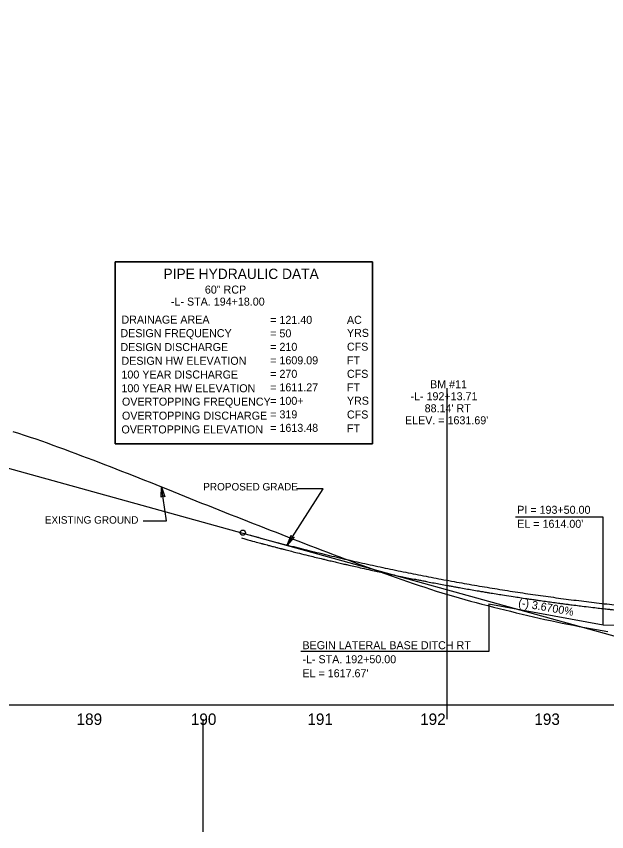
# Model space of a CAD drawing. Extents: x 498575 to 532350, y 405181 to 484585.
# Drawn here: x 523656 to 524172, y 483123 to 483836 of the extents above; entities that cross this region are included whole.
import ezdxf

# ---------------------------------------------------------------- set-up
doc = ezdxf.new("R2010")
doc.units = 0
for name, color, linetype in [('Exist Profile Cell', 7, 'Continuous'), ('Exist Vertical Profile Ground Line', 7, 'Continuous'), ('Exist Vertical Profile Horizontal Axis Label Major', 7, 'Continuous'), ('Prop Grid Mask', 7, 'Continuous'), ('Prop PFL Text', 7, 'Continuous'), ('Prop Vertical Profile Curve Label', 7, 'Continuous'), ('Prop Vertical Profile Ditch Grade Right', 7, 'Continuous'), ('Prop Vertical Profile Ditch Grade Right Label', 7, 'Continuous'), ('Prop Vertical Profile Grade', 7, 'Continuous'), ('Prop VPI Label', 7, 'Continuous'), ('Scratch_Level_0', 7, 'Continuous'), ('Scratch_Level_6', 7, 'Continuous'), ('Sheet Data Text CELL', 7, 'Continuous'), ('Sheet Profile Grid Minor CELL', 7, 'Continuous')]:
    doc.layers.add(name, color=color, linetype=linetype)

msp = doc.modelspace()

# ---------------------------------------------------------------- linework, layer by layer
at = {"layer": 'Exist Profile Cell'}
msp.add_line((505856.74, 483233.71), (526056.74, 483233.71), dxfattribs=at)
at = {"layer": 'Exist Vertical Profile Ground Line'}
for points in [[(523653.15, 483472.83), (523658.15, 483471.2), (523663.15, 483469.54), (523668.15, 483467.88), (523673.15, 483466.16), (523678.15, 483464.44), (523683.15, 483462.67), (523688.15, 483460.89), (523693.15, 483459.08), (523698.15, 483457.21), (523703.15, 483455.32), (523708.15, 483453.42), (523713.15, 483451.55), (523718.15, 483449.7), (523723.15, 483447.82), (523728.15, 483445.91), (523733.15, 483443.99), (523738.15, 483442.05), (523743.15, 483440.07), (523748.15, 483438.1), (523753.15, 483436.15), (523758.15, 483434.19), (523763.15, 483432.26), (523768.15, 483430.3), (523773.15, 483428.31), (523778.15, 483426.32), (523783.15, 483424.31), (523788.15, 483422.3), (523793.15, 483420.26), (523798.15, 483418.2), (523803.15, 483416.18), (523808.15, 483414.15), (523813.15, 483412.15)], [(523813.15, 483412.15), (523818.15, 483410.17), (523823.15, 483408.19), (523828.15, 483406.19), (523833.15, 483404.2), (523838.15, 483402.21), (523843.15, 483400.22), (523848.15, 483398.26), (523853.15, 483396.29), (523858.15, 483394.33), (523863.15, 483392.39), (523868.15, 483390.42), (523873.15, 483388.47), (523878.15, 483386.52), (523883.15, 483384.57), (523888.15, 483382.6), (523893.15, 483380.65), (523898.15, 483378.72), (523903.15, 483376.76), (523908.15, 483374.8), (523913.15, 483372.85), (523918.15, 483370.92), (523923.15, 483369), (523928.15, 483367.1), (523933.15, 483365.23), (523938.15, 483363.34), (523943.15, 483361.49), (523948.15, 483359.62), (523953.15, 483357.75), (523958.15, 483355.89), (523963.15, 483354.07), (523968.15, 483352.29), (523973.15, 483350.47), (523978.15, 483348.69), (523983.15, 483346.9), (523988.15, 483345.15), (523993.15, 483343.38), (523998.15, 483341.61), (524003.15, 483339.89), (524008.15, 483338.19), (524013.15, 483336.52), (524018.15, 483334.89), (524023.15, 483333.28), (524028.15, 483331.73), (524033.15, 483330.21), (524038.15, 483328.73), (524043.15, 483327.3), (524048.15, 483325.89), (524053.15, 483324.49), (524058.15, 483323.13), (524063.15, 483321.79), (524068.15, 483320.52), (524073.15, 483319.22), (524078.15, 483318), (524083.15, 483316.78), (524088.15, 483315.55), (524093.15, 483314.32), (524098.15, 483313.1), (524103.15, 483311.9), (524108.15, 483310.76), (524113.15, 483309.6), (524118.15, 483308.45), (524123.15, 483307.38), (524128.15, 483306.34), (524133.15, 483305.29), (524138.15, 483304.3), (524143.15, 483303.32), (524148.15, 483302.35), (524153.15, 483301.42), (524158.15, 483300.49), (524163.15, 483299.58), (524168.15, 483298.72), (524173.15, 483297.84)]]:
    msp.add_lwpolyline(points, dxfattribs=at)
at = {"layer": 'Prop Grid Mask'}
msp.add_lwpolyline([(523742.45, 483620.91), (523967.45, 483620.91), (523967.45, 483461.91), (523742.45, 483461.91)], close=True, dxfattribs=at)
at = {"layer": 'Prop PFL Text'}
for p, q in [((523787.28, 483394.7), (523783.15, 483424.31)), ((523892.93, 483373.48), (523924.46, 483422.67)), ((523924.46, 483422.67), (523901.04, 483422.67)), ((523766.92, 483394.7), (523787.28, 483394.7))]:
    msp.add_line(p, q, dxfattribs=at)
for points in [[(523782.87, 483415.19), (523783.15, 483424.31), (523785.99, 483415.57), (523784.25, 483416.49)], [(523899.04, 483380.27), (523892.93, 483373.48), (523896.4, 483381.99), (523897.14, 483380.16)]]:
    msp.add_lwpolyline(points, close=True, dxfattribs=at)
at = {"layer": 'Prop Vertical Profile Curve Label'}
msp.add_circle((523854.08, 483384.26), 2.25, dxfattribs=at)
at = {"layer": 'Prop Vertical Profile Ditch Grade Right'}
msp.add_lwpolyline([(524069.08, 483322.06), (524169.08, 483303.71), (524239.08, 483302.66), (524239.08, 483302.66)], dxfattribs=at)
at = {"layer": 'Prop Vertical Profile Ditch Grade Right Label'}
for p, q in [((524169.08, 483397.85), (524092.59, 483397.85)), ((524169.08, 483303.71), (524169.08, 483397.85)), ((524069.08, 483322.06), (524069.08, 483280.47)), ((524069.08, 483280.47), (523904.91, 483280.47))]:
    msp.add_line(p, q, dxfattribs=at)
at = {"layer": 'Prop Vertical Profile Grade'}
msp.add_line((522224.08, 483835.63), (523854.08, 483383.86), dxfattribs=at)
msp.add_spline([(523854.08, 483383.86), (523871.88, 483379), (523889.68, 483374.32), (523907.48, 483369.8), (523925.28, 483365.44), (523943.08, 483361.24), (523960.88, 483357.22), (523978.68, 483353.35), (523996.48, 483349.65), (524014.28, 483346.12), (524032.08, 483342.75), (524049.88, 483339.54), (524067.68, 483336.5), (524085.48, 483333.62), (524103.28, 483330.91), (524121.08, 483328.36), (524138.88, 483325.98), (524156.68, 483323.76), (524174.48, 483321.71), (524192.28, 483319.82), (524210.08, 483318.09), (524227.88, 483316.53), (524245.68, 483315.13), (524254.26, 483314.52)], degree=3, dxfattribs=at)
at = {"layer": 'Prop VPI Label'}
msp.add_line((523854.08, 483383.86), (524296.43, 483261.25), dxfattribs=at)
at = {"layer": 'Scratch_Level_0'}
msp.add_line((524032.79, 483221.21), (524032.79, 483510.52), dxfattribs=at)
at = {"layer": 'Scratch_Level_6'}
msp.add_open_spline([(523852.93, 483379.63), (523857.44, 483378.4), (523863.09, 483376.87), (523869.02, 483375.25), (523870.43, 483374.86), (523870.74, 483374.78), (523870.78, 483374.77), (523870.85, 483374.75), (523870.96, 483374.72), (523871.21, 483374.65), (523871.99, 483374.44), (523872.7, 483374.25), (523875.54, 483373.49), (523877.81, 483372.88), (523882.35, 483371.7), (523884.62, 483371.11), (523887.17, 483370.45), (523887.6, 483370.34), (523888.09, 483370.21), (523888.34, 483370.14), (523888.45, 483370.12), (523888.52, 483370.1), (523888.55, 483370.09), (523889.16, 483369.93), (523890.86, 483369.49), (523892.56, 483369.06), (523898.24, 483367.6), (523902.79, 483366.45), (523911.89, 483364.19), (523916.45, 483363.07), (523923.29, 483361.41), (523925.57, 483360.87), (523930.13, 483359.78), (523934.7, 483358.7), (523939.27, 483357.63), (523943.84, 483356.58), (523946.12, 483356.05), (523952.98, 483354.49), (523957.56, 483353.47), (523966.72, 483351.44), (523971.31, 483350.45), (523978.19, 483348.98), (523980.48, 483348.5), (523985.08, 483347.53), (523987.37, 483347.05), (523994.26, 483345.63), (523998.86, 483344.7), (524005.76, 483343.33), (524008.06, 483342.87), (524012.67, 483341.97), (524014.97, 483341.53), (524021.88, 483340.2), (524026.49, 483339.33), (524033.41, 483338.05), (524035.72, 483337.63), (524040.33, 483336.79), (524042.64, 483336.38), (524049.57, 483335.15), (524054.19, 483334.34), (524061.13, 483333.16), (524063.44, 483332.77), (524068.07, 483332), (524070.39, 483331.62), (524077.33, 483330.48), (524081.96, 483329.74), (524091.23, 483328.3), (524095.87, 483327.59), (524102.83, 483326.55), (524105.15, 483326.21), (524109.8, 483325.54), (524112.12, 483325.2), (524119.08, 483324.22), (524123.73, 483323.57), (524130.71, 483322.64), (524133.03, 483322.33), (524137.68, 483321.72), (524140.01, 483321.42), (524146.99, 483320.53), (524151.65, 483319.96), (524160.96, 483318.84), (524165.62, 483318.3), (524172.62, 483317.51), (524174.95, 483317.25), (524179.61, 483316.74), (524181.95, 483316.49), (524188.94, 483315.75), (524193.61, 483315.28), (524200.61, 483314.59), (524202.95, 483314.37), (524207.62, 483313.92), (524209.96, 483313.71), (524216.97, 483313.07), (524221.64, 483312.66), (524228.65, 483312.07), (524230.99, 483311.88), (524235.67, 483311.51), (524238.01, 483311.33), (524245.02, 483310.79), (524249.7, 483310.45), (524256.72, 483309.96), (524259.06, 483309.81), (524263.74, 483309.5), (524266.09, 483309.35), (524273.11, 483308.92), (524277.79, 483308.64), (524287.16, 483308.13), (524291.85, 483307.89), (524298.88, 483307.56), (524301.22, 483307.45), (524305.91, 483307.25), (524308.25, 483307.15), (524315.29, 483306.87), (524319.97, 483306.7), (524327.01, 483306.47), (524329.35, 483306.4), (524334.04, 483306.26), (524336.39, 483306.2), (524343.42, 483306.02), (524348.11, 483305.92), (524357.5, 483305.75), (524362.19, 483305.68), (524371.57, 483305.58), (524376.26, 483305.54), (524385.65, 483305.51), (524390.34, 483305.51), (524399.72, 483305.54), (524404.41, 483305.58), (524413.8, 483305.68), (524418.49, 483305.75), (524427.87, 483305.92), (524432.56, 483306.03), (524439.59, 483306.21), (524441.94, 483306.27), (524446.63, 483306.41), (524448.97, 483306.48), (524456.01, 483306.71), (524460.7, 483306.88), (524467.73, 483307.17), (524470.07, 483307.26), (524474.76, 483307.47), (524477.1, 483307.58), (524484.13, 483307.91), (524488.82, 483308.15), (524498.19, 483308.66), (524502.87, 483308.94), (524509.9, 483309.37), (524512.24, 483309.52), (524516.92, 483309.83), (524519.26, 483309.99), (524526.28, 483310.47), (524530.96, 483310.82), (524537.98, 483311.35), (524540.31, 483311.54), (524544.99, 483311.91), (524547.33, 483312.1), (524554.34, 483312.69), (524559.02, 483313.1), (524566.02, 483313.74), (524568.36, 483313.96), (524573.03, 483314.4), (524575.37, 483314.62), (524582.37, 483315.31), (524587.04, 483315.79), (524594.03, 483316.53), (524596.37, 483316.78), (524601.03, 483317.29), (524603.36, 483317.55), (524610.36, 483318.34), (524615.02, 483318.88), (524624.33, 483320), (524628.99, 483320.58), (524635.97, 483321.46), (524638.3, 483321.76), (524642.95, 483322.37), (524645.27, 483322.68), (524652.25, 483323.62), (524656.89, 483324.26), (524663.86, 483325.25), (524666.18, 483325.59), (524670.83, 483326.26), (524673.15, 483326.6), (524680.11, 483327.64), (524684.74, 483328.35), (524694.01, 483329.8), (524698.65, 483330.54), (524704.43, 483331.48), (524706.17, 483331.77), (524708.05, 483332.08), (524708.85, 483332.21), (524709.06, 483332.25), (524709.21, 483332.27), (524709.28, 483332.28), (524709.64, 483332.34), (524709.93, 483332.39), (524712.53, 483332.83), (524714.84, 483333.21), (524719.47, 483333.99), (524721.79, 483334.39), (524724.68, 483334.9), (524725.26, 483335.01), (524726.13, 483335.16), (524726.49, 483335.23), (524726.89, 483335.3), (524727, 483335.32), (524727.07, 483335.33), (524727.11, 483335.34), (524727.29, 483335.37), (524728.58, 483335.6), (524734.49, 483336.67), (524740.25, 483337.71), (524744.85, 483338.54)], degree=3, dxfattribs=at)
at = {"layer": 'Sheet Data Text CELL'}
msp.add_lwpolyline([(523742.45, 483461.91), (523967.45, 483461.91), (523967.45, 483620.91), (523742.45, 483620.91)], close=True, dxfattribs=at)
at = {"layer": 'Sheet Profile Grid Minor CELL'}
msp.add_line((523819.08, 483221.21), (523819.08, 483122.89), dxfattribs=at)

# ---------------------------------------------------------------- texts
at = {"layer": 'Exist Vertical Profile Horizontal Axis Label Major'}
for s, p in [('189', (523708.83, 483216.21)), ('189', (523708.83, 483216.21)), ('190', (523808.7, 483216.21)), ('190', (523808.71, 483216.21)), ('191', (523910.54, 483216.21)), ('191', (523910.55, 483216.21)), ('192', (524009.09, 483216.21)), ('192', (524009.1, 483216.21)), ('193', (524108.93, 483216.21)), ('193', (524108.93, 483216.21))]:
    msp.add_text(s, height=10, dxfattribs=at).set_placement(p)
at = {"layer": 'Prop PFL Text'}
for s, height, p in [('BM #11', 7, (524017.79, 483510.52)), ('-L- 192+13.71', 7, (524000.66, 483500.02)), ("88.14' RT", 7, (524013.06, 483489.52)), ("ELEV. = 1631.69'", 7, (523995.84, 483479.02)), ('PROPOSED GRADE', 6.5157, (523819.52, 483421.17)), ('EXISTING GROUND', 6.5157, (523681.05, 483392.15))]:
    msp.add_text(s, height=height, dxfattribs=at).set_placement(p)
at = {"layer": 'Prop Vertical Profile Ditch Grade Right Label'}
for s, rotation, p in [('PI = 193+50.00', 360, (524093.97, 483400.76)), ("EL = 1614.00'", 360, (524093.97, 483388.51)), ('(-) 3.6700%', 350.13774, (524094.52, 483319.93)), ('BEGIN LATERAL BASE DITCH RT', 360, (523906.22, 483282.38)), ('-L- STA. 192+50.00', 360, (523906.22, 483270.13)), ("EL = 1617.67'", 360, (523906.22, 483257.88))]:
    msp.add_text(s, height=7, rotation=rotation, dxfattribs=at).set_placement(p)
at = {"layer": 'Sheet Data Text CELL'}
for s, height, p in [('PIPE HYDRAULIC DATA', 8.9997, (523784.75, 483606.02)), ('DRAINAGE AREA', 6.9999, (523748.03, 483567.01)), ('AC', 7, (523945.12, 483566.81)), ('DESIGN FREQUENCY', 6.9999, (523747.13, 483555.16)), ('= 50', 7, (523878.06, 483555.01)), ('YRS', 7, (523945.12, 483555.41)), ('CFS', 7, (523945.12, 483543.36)), ('DESIGN DISCHARGE', 6.9999, (523747.13, 483543.01)), ('DESIGN HW ELEVATION', 6.9999, (523748.03, 483531.01)), ('FT', 7, (523945.12, 483531.41)), ('100 YEAR DISCHARGE', 6.9999, (523748.03, 483519.01)), ('CFS', 7, (523945.12, 483519.61)), ('FT', 7, (523945.12, 483507.81)), ('100 YEAR HW ELEVATION', 6.9999, (523748.03, 483507.01)), ('OVERTOPPING FREQUENCY', 6.9999, (523748.48, 483495.31)), ('YRS', 7, (523945.12, 483496.11)), ('OVERTOPPING DISCHARGE', 6.9999, (523748.48, 483483.06)), ('CFS', 7, (523945.12, 483484.06)), ('FT', 7, (523945.12, 483472.01)), ('OVERTOPPING ELEVATION', 6.9999, (523748.03, 483471.01))]:
    msp.add_text(s, height=height, rotation=360, dxfattribs=at).set_placement(p)
for s, p in [('60" RCP', (523820.96, 483593.25)), ('   -L- STA. 194+18.00', (523783.48, 483582.75)), ('= 121.40', (523878.06, 483566.81)), ('= 210', (523878.06, 483543.21)), ('= 1609.09', (523878.06, 483531.41)), ('= 270', (523878.06, 483519.61)), ('= 1611.27', (523878.06, 483507.81)), ('= 100+', (523878.06, 483496.01)), ('= 319', (523878.06, 483484.21)), ('= 1613.48', (523878.06, 483472.41))]:
    msp.add_text(s, height=7, dxfattribs=at).set_placement(p)

doc.saveas('drawing.dxf')
